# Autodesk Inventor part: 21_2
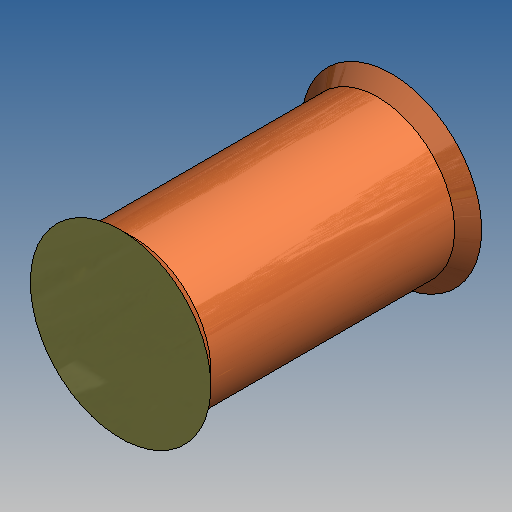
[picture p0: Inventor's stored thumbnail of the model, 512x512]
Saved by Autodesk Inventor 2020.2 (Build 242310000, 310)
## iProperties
Part Number: 21_2
Material: Generic
Document SubType Name: Modeling
Designer: amoles
Appearance: Default
Author: amoles
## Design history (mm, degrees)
feature "Base1"
body "Solid1"
